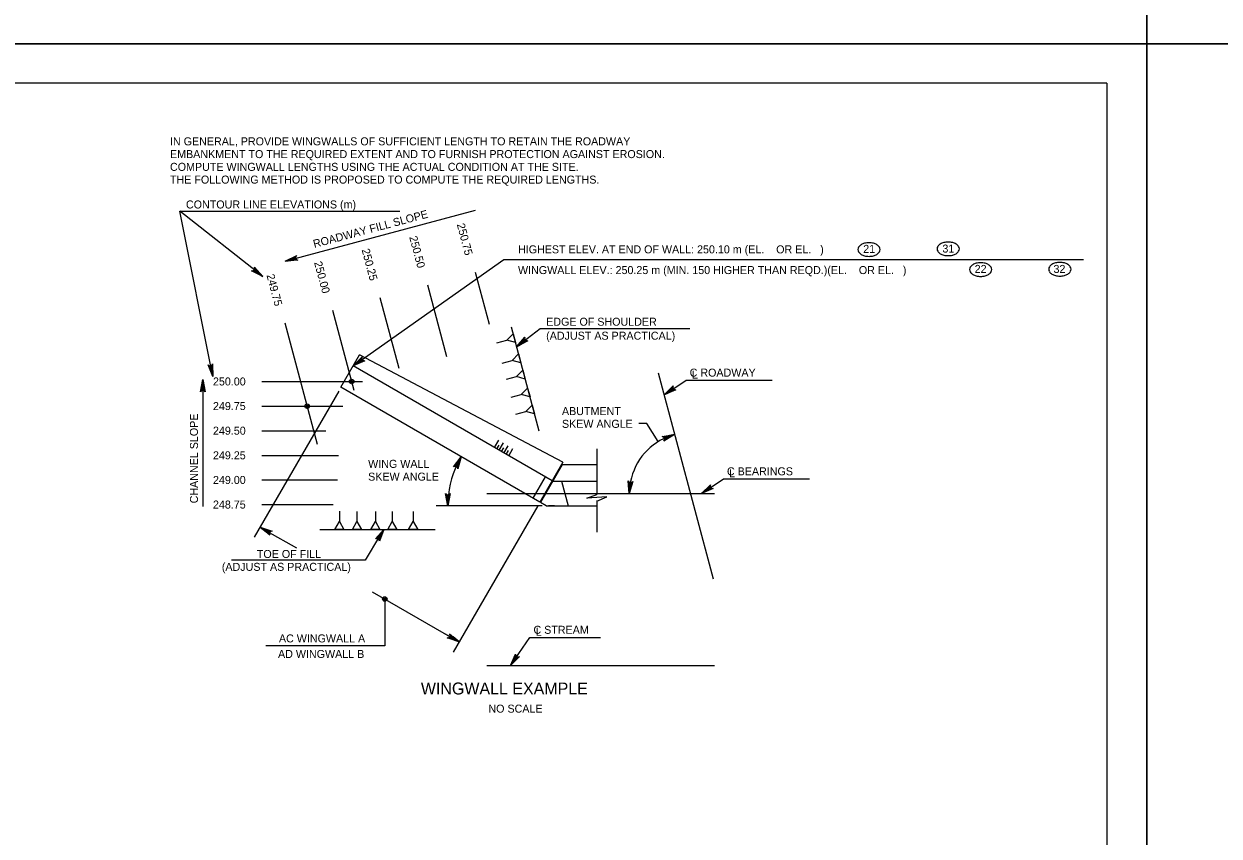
# Model space of a CAD drawing. Extents: x -5022 to -159, y 1126 to 7226.
# Drawn here: x -1737.9 to -1290, y 3798.9 to 4103.3 of the extents above; entities that cross this region are included whole.
import ezdxf

# ---------------------------------------------------------------- set-up
doc = ezdxf.new("R2010")
doc.units = 0
for name, color, linetype in [('2', 7, 'Continuous'), ('3', 7, 'Continuous'), ('4', 7, 'Continuous'), ('5', 7, 'Continuous'), ('6', 7, 'Continuous'), ('PLT-BNDY', 7, 'Continuous')]:
    doc.layers.add(name, color=color, linetype=linetype)

msp = doc.modelspace()

# ---------------------------------------------------------------- linework, layer by layer
at = {"layer": '2'}
for p, q in [((-1332.13, 4081.14), (-2118.13, 4081.14)), ((-1332.13, 4081.14), (-1332.13, 3517.14)), ((-1563.5, 3990.58), (-1568.7, 4010.1)), ((-1579.37, 3978.49), (-1586.53, 4005.35)), ((-1597.31, 3974.14), (-1604.37, 4000.6)), ((-1614.2, 3965.85), (-1622.2, 3995.84)), ((-1627.92, 3945.65), (-1640.03, 3991.09)), ((-1544.86, 3950.71), (-1555.24, 3989.67)), ((-1560.7, 3983.75), (-1556.99, 3984.74)), ((-1558.69, 3976.2), (-1554.97, 3977.19)), ((-1648.81, 3969.27), (-1611.06, 3969.27)), ((-1557.06, 3970.1), (-1553.35, 3971.09)), ((-1555.27, 3963.39), (-1551.56, 3964.38)), ((-1648.81, 3960.04), (-1618.35, 3960.04)), ((-1553.58, 3957.03), (-1549.86, 3958.02)), ((-1648.81, 3950.81), (-1624.83, 3950.81)), ((-1561.58, 3944.52), (-1559.99, 3947.26)), ((-1559.8, 3943.5), (-1558.22, 3946.23)), ((-1560.69, 3944.01), (-1559.88, 3945.41)), ((-1558.91, 3942.98), (-1558.1, 3944.39)), ((-1558.02, 3942.47), (-1556.45, 3945.21)), ((-1557.14, 3941.96), (-1556.33, 3943.36)), ((-1556.25, 3941.45), (-1554.67, 3944.19)), ((-1648.81, 3941.59), (-1619.97, 3941.59)), ((-1648.81, 3932.36), (-1620.37, 3932.36)), ((-1648.81, 3923.13), (-1621.99, 3923.13)), ((-1619.7, 3920.62), (-1619.71, 3916.77)), ((-1613.12, 3920.61), (-1613.12, 3916.76)), ((-1606.18, 3920.6), (-1606.18, 3916.76)), ((-1599.86, 3920.59), (-1599.86, 3916.75)), ((-1592.04, 3920.58), (-1592.05, 3916.74)), ((-1627.03, 3913.82), (-1583.78, 3913.82))]:
    msp.add_line(p, q, dxfattribs=at)
for points in [[(-1554.57, 3987.15), (-1553.69, 3983.86), (-1556.99, 3984.74)], [(-1552.56, 3979.6), (-1551.68, 3976.31), (-1554.97, 3977.19)], [(-1550.93, 3973.5), (-1550.05, 3970.2), (-1553.35, 3971.09)], [(-1549.14, 3966.79), (-1548.26, 3963.49), (-1551.56, 3964.38)], [(-1547.45, 3960.43), (-1546.57, 3957.13), (-1549.86, 3958.02)], [(-1618.01, 3913.82), (-1621.42, 3913.82), (-1619.71, 3916.77)], [(-1611.42, 3913.81), (-1614.83, 3913.81), (-1613.12, 3916.76)], [(-1604.48, 3913.8), (-1607.89, 3913.8), (-1606.18, 3916.76)], [(-1598.16, 3913.79), (-1601.57, 3913.8), (-1599.86, 3916.75)], [(-1590.35, 3913.78), (-1593.76, 3913.78), (-1592.05, 3916.74)]]:
    msp.add_lwpolyline(points, close=True, dxfattribs=at)
at = {"layer": '3'}
for p, q in [((-1679.45, 4033.13), (-1597.01, 4033.13)), ((-1558.01, 4015.05), (-1555.01, 4015.05)), ((-1555.01, 4015.05), (-1340.86, 4015.05)), ((-1550.92, 3984.17), (-1544.46, 3989.18)), ((-1544.46, 3989.18), (-1488.37, 3989.18)), ((-1495.5, 3965.92), (-1489.76, 3969.76)), ((-1489.76, 3969.76), (-1457.46, 3969.76)), ((-1619.95, 3965.7), (-1651.6, 3910.88)), ((-1504.42, 3953.52), (-1507.42, 3953.52)), ((-1500.21, 3946.74), (-1504.42, 3953.52)), ((-1481.53, 3928.93), (-1475.79, 3932.77)), ((-1475.79, 3932.77), (-1443.48, 3932.77)), ((-1543.73, 3922.67), (-1583.46, 3922.67)), ((-1545.32, 3922.71), (-1577.01, 3867.82)), ((-1646.83, 3913.24), (-1635.81, 3906.88)), ((-1604.61, 3911.25), (-1610, 3902.28)), ((-1613, 3902.28), (-1660.1, 3902.28)), ((-1610, 3902.28), (-1613, 3902.28)), ((-1607.39, 3890.47), (-1577.35, 3873.13)), ((-1602.68, 3887.75), (-1602.68, 3870.24)), ((-1577.35, 3873.13), (-1579.91, 3874.6)), ((-1602.68, 3870.24), (-1647.27, 3870.24)), ((-1553.87, 3865.28), (-1548.29, 3873.37)), ((-1548.29, 3873.37), (-1521.82, 3873.37))]:
    msp.add_line(p, q, dxfattribs=at)
for points in [[(-1648.42, 4008.6), (-1679.45, 4033.13)], [(-1667.17, 3971.15), (-1679.45, 4033.13)], [(-1639.98, 4014.42), (-1568.65, 4033.43)], [(-1639.98, 4014.42), (-1635.7, 4016.46), (-1635.99, 4016.13), (-1636.09, 4015.78), (-1636.06, 4015.46), (-1635.92, 4015.17), (-1635.67, 4014.92), (-1635.25, 4014.77), (-1639.98, 4014.42), (-1635.67, 4014.92), (-1635.92, 4015.17), (-1639.98, 4014.42), (-1636.06, 4015.46), (-1636.09, 4015.78), (-1639.98, 4014.42), (-1635.99, 4016.13)], [(-1614.52, 3975.09), (-1558.01, 4015.05)], [(-1648.42, 4008.6), (-1652.62, 4010.81), (-1652.19, 4010.78), (-1651.85, 4010.91), (-1651.61, 4011.12), (-1651.46, 4011.4), (-1651.41, 4011.76), (-1651.54, 4012.18), (-1648.42, 4008.6), (-1651.41, 4011.76), (-1651.46, 4011.4), (-1648.42, 4008.6), (-1651.61, 4011.12), (-1651.85, 4010.91), (-1648.42, 4008.6), (-1652.19, 4010.78)], [(-1553.29, 3982.33), (-1550.14, 3985.88), (-1550.27, 3985.47), (-1550.23, 3985.1), (-1550.08, 3984.82), (-1549.84, 3984.61), (-1549.51, 3984.48), (-1549.07, 3984.5), (-1553.29, 3982.33), (-1549.51, 3984.48), (-1549.84, 3984.61), (-1553.29, 3982.33), (-1550.08, 3984.82), (-1550.23, 3985.1), (-1553.29, 3982.33), (-1550.27, 3985.47)], [(-1614.52, 3975.09), (-1611.22, 3978.5), (-1611.37, 3978.09), (-1611.34, 3977.72), (-1611.21, 3977.44), (-1610.98, 3977.21), (-1610.65, 3977.06), (-1610.21, 3977.07), (-1614.52, 3975.09), (-1610.65, 3977.06), (-1610.98, 3977.21), (-1614.52, 3975.09), (-1611.21, 3977.44), (-1611.34, 3977.72), (-1614.52, 3975.09), (-1611.37, 3978.09)], [(-1667.17, 3971.15), (-1668.93, 3975.56), (-1668.62, 3975.25), (-1668.28, 3975.13), (-1667.96, 3975.14), (-1667.66, 3975.25), (-1667.39, 3975.5), (-1667.22, 3975.89), (-1667.17, 3971.15), (-1667.39, 3975.5), (-1667.66, 3975.25), (-1667.17, 3971.15), (-1667.96, 3975.14), (-1668.28, 3975.13), (-1667.17, 3971.15), (-1668.62, 3975.25)], [(-1670.85, 3970.05), (-1669.97, 3965.39), (-1670.22, 3965.75), (-1670.53, 3965.93), (-1670.85, 3965.98), (-1671.16, 3965.93), (-1671.47, 3965.75), (-1671.72, 3965.39), (-1670.85, 3970.05), (-1671.47, 3965.75), (-1671.16, 3965.93), (-1670.85, 3970.05), (-1670.85, 3965.98), (-1670.53, 3965.93), (-1670.85, 3970.05), (-1670.22, 3965.75)], [(-1670.85, 3970.05), (-1670.85, 3922.37)], [(-1497.96, 3964.28), (-1494.57, 3967.59), (-1494.73, 3967.19), (-1494.71, 3966.83), (-1494.58, 3966.54), (-1494.36, 3966.31), (-1494.03, 3966.15), (-1493.6, 3966.14), (-1497.96, 3964.28), (-1494.03, 3966.15), (-1494.36, 3966.31), (-1497.96, 3964.28), (-1494.58, 3966.54), (-1494.71, 3966.83), (-1497.96, 3964.28), (-1494.73, 3967.19)], [(-1494.07, 3949.42), (-1498.13, 3946.97), (-1497.88, 3947.33), (-1497.82, 3947.69), (-1497.88, 3948), (-1498.03, 3948.27), (-1498.32, 3948.5), (-1498.74, 3948.61), (-1494.07, 3949.42), (-1498.32, 3948.5), (-1498.03, 3948.27), (-1494.07, 3949.42), (-1497.88, 3948), (-1497.82, 3947.69), (-1494.07, 3949.42), (-1497.88, 3947.33)], [(-1574.09, 3941.09), (-1575.3, 3936.51), (-1575.37, 3936.94), (-1575.57, 3937.24), (-1575.83, 3937.42), (-1576.14, 3937.51), (-1576.5, 3937.47), (-1576.88, 3937.26), (-1574.09, 3941.09), (-1576.5, 3937.47), (-1576.14, 3937.51), (-1574.09, 3941.09), (-1575.83, 3937.42), (-1575.57, 3937.24), (-1574.09, 3941.09), (-1575.37, 3936.94)], [(-1511.04, 3927.29), (-1511.48, 3932.01), (-1511.26, 3931.63), (-1510.97, 3931.41), (-1510.66, 3931.33), (-1510.35, 3931.36), (-1510.02, 3931.51), (-1509.74, 3931.85), (-1511.04, 3927.29), (-1510.02, 3931.51), (-1510.35, 3931.36), (-1511.04, 3927.29), (-1510.66, 3931.33), (-1510.97, 3931.41), (-1511.04, 3927.29), (-1511.26, 3931.63)], [(-1483.98, 3927.29), (-1480.6, 3930.6), (-1480.76, 3930.2), (-1480.74, 3929.83), (-1480.61, 3929.54), (-1480.39, 3929.31), (-1480.06, 3929.16), (-1479.62, 3929.15), (-1483.98, 3927.29), (-1480.06, 3929.16), (-1480.39, 3929.31), (-1483.98, 3927.29), (-1480.61, 3929.54), (-1480.74, 3929.83), (-1483.98, 3927.29), (-1480.76, 3930.2)], [(-1579.03, 3922.67), (-1579.9, 3927.33), (-1579.65, 3926.98), (-1579.34, 3926.79), (-1579.03, 3926.73), (-1578.71, 3926.79), (-1578.4, 3926.98), (-1578.15, 3927.33), (-1579.03, 3922.67), (-1578.4, 3926.98), (-1578.71, 3926.79), (-1579.03, 3922.67), (-1579.03, 3926.73), (-1579.34, 3926.79), (-1579.03, 3922.67), (-1579.65, 3926.98)], [(-1649.38, 3914.72), (-1644.91, 3913.14), (-1645.34, 3913.11), (-1645.66, 3912.93), (-1645.86, 3912.68), (-1645.97, 3912.39), (-1645.97, 3912.02), (-1645.78, 3911.63), (-1649.38, 3914.72), (-1645.97, 3912.02), (-1645.97, 3912.39), (-1649.38, 3914.72), (-1645.86, 3912.68), (-1645.66, 3912.93), (-1649.38, 3914.72), (-1645.34, 3913.11)], [(-1603.07, 3913.82), (-1604.72, 3909.37), (-1604.75, 3909.81), (-1604.92, 3910.13), (-1605.16, 3910.34), (-1605.46, 3910.45), (-1605.82, 3910.45), (-1606.22, 3910.27), (-1603.07, 3913.82), (-1605.82, 3910.45), (-1605.46, 3910.45), (-1603.07, 3913.82), (-1605.16, 3910.34), (-1604.92, 3910.13), (-1603.07, 3913.82), (-1604.75, 3909.81)], [(-1574.8, 3871.65), (-1579.27, 3873.23), (-1578.83, 3873.26), (-1578.52, 3873.44), (-1578.32, 3873.68), (-1578.21, 3873.98), (-1578.21, 3874.34), (-1578.4, 3874.74), (-1574.8, 3871.65), (-1578.21, 3874.34), (-1578.21, 3873.98), (-1574.8, 3871.65), (-1578.32, 3873.68), (-1578.52, 3873.44), (-1574.8, 3871.65), (-1578.83, 3873.26)], [(-1555.58, 3862.81), (-1553.65, 3867.14), (-1553.65, 3866.7), (-1553.5, 3866.37), (-1553.27, 3866.15), (-1552.98, 3866.02), (-1552.62, 3865.99), (-1552.21, 3866.15), (-1555.58, 3862.81), (-1552.62, 3865.99), (-1552.98, 3866.02), (-1555.58, 3862.81), (-1553.27, 3866.15), (-1553.5, 3866.37), (-1555.58, 3862.81), (-1553.65, 3866.7)]]:
    msp.add_lwpolyline(points, dxfattribs=at)
for points in [[(-1639.98, 4014.42), (-1637.02, 4014.95), (-1637.15, 4015.43)], [(-1648.42, 4008.6), (-1650.62, 4010.66), (-1650.93, 4010.26)], [(-1550.61, 3983.78), (-1551.22, 3984.57), (-1553.29, 3982.33)], [(-1667.17, 3971.15), (-1667.51, 3974.15), (-1668, 3974.05)], [(-1614.52, 3975.09), (-1611.93, 3976.62), (-1612.22, 3977.03)], [(-1670.85, 3970.05), (-1671.1, 3967.05), (-1670.6, 3967.05)], [(-1495.77, 3966.33), (-1495.23, 3965.51), (-1497.96, 3964.28)], [(-1496.7, 3947.99), (-1497.02, 3948.93), (-1494.07, 3949.41)], [(-1575.9, 3938.71), (-1575.03, 3938.25), (-1574.09, 3941.09)], [(-1511.34, 3930.27), (-1510.36, 3930.2), (-1511.04, 3927.29)], [(-1481.8, 3929.34), (-1481.26, 3928.52), (-1483.98, 3927.29)], [(-1578.41, 3925.6), (-1579.4, 3925.64), (-1579.03, 3922.67)], [(-1646.58, 3913.67), (-1647.07, 3912.81), (-1649.38, 3914.72)], [(-1605.04, 3911.51), (-1604.18, 3910.99), (-1603.07, 3913.82)], [(-1577.11, 3873.55), (-1577.6, 3872.7), (-1574.8, 3871.65)], [(-1553.46, 3864.99), (-1554.29, 3865.56), (-1555.58, 3862.81)]]:
    msp.add_lwpolyline(points, close=True, dxfattribs=at)
for radius in [0.833, 0.417]:
    msp.add_circle((-1602.68, 3887.75), radius, dxfattribs=at)
for centre, radius, start, end in [((-1423.79, 4018.74), 1.61, 145.8704, 180), ((-1423.79, 4018.74), 1.61, 180, 214.1296), ((-1422.56, 4017.9), 3.1, 121.4296, 145.8704), ((-1421.75, 4016.57), 4.65, 104.2049, 121.4296), ((-1421.21, 4014.47), 6.82, 90, 104.2049), ((-1421.21, 4014.47), 6.82, 75.7951, 90), ((-1420.68, 4016.57), 4.65, 58.5704, 75.7951), ((-1419.87, 4017.9), 3.1, 34.1296, 58.5704), ((-1418.64, 4018.74), 1.61, 0, 34.1296), ((-1418.64, 4018.74), 1.61, 325.8704, 0), ((-1394.11, 4018.99), 1.61, 145.8704, 180), ((-1394.11, 4018.99), 1.61, 180, 214.1296), ((-1392.88, 4018.16), 3.1, 121.4296, 145.8704), ((-1392.88, 4019.82), 3.1, 214.1296, 238.5704), ((-1392.07, 4016.83), 4.65, 104.2049, 121.4296), ((-1391.54, 4014.72), 6.82, 90, 104.2049), ((-1391.54, 4014.72), 6.82, 75.7951, 90), ((-1391, 4016.83), 4.65, 58.5704, 75.7951), ((-1390.19, 4018.16), 3.1, 34.1296, 58.5704), ((-1390.19, 4019.82), 3.1, 301.4296, 325.8704), ((-1388.96, 4018.99), 1.61, 0, 34.1296), ((-1388.96, 4018.99), 1.61, 325.8704, 0), ((-1422.56, 4019.57), 3.1, 214.1296, 238.5704), ((-1421.75, 4020.9), 4.65, 238.5704, 255.7951), ((-1421.21, 4023), 6.82, 255.7951, 270), ((-1421.21, 4023), 6.82, 270, 284.2049), ((-1420.68, 4020.9), 4.65, 284.2049, 301.4296), ((-1419.87, 4019.57), 3.1, 301.4296, 325.8704), ((-1392.07, 4021.15), 4.65, 238.5704, 255.7951), ((-1391.54, 4023.26), 6.82, 255.7951, 270), ((-1391.54, 4023.26), 6.82, 270, 284.2049), ((-1391, 4021.15), 4.65, 284.2049, 301.4296), ((-1379.9, 4009.06), 4.65, 104.2049, 121.4296), ((-1379.36, 4006.96), 6.82, 90, 104.2049), ((-1379.36, 4006.96), 6.82, 75.7951, 90), ((-1378.83, 4009.06), 4.65, 58.5704, 75.7951), ((-1350.22, 4009.19), 4.65, 104.2049, 121.4296), ((-1349.68, 4007.08), 6.82, 90, 104.2049), ((-1349.68, 4007.08), 6.82, 75.7951, 90), ((-1349.15, 4009.19), 4.65, 58.5704, 75.7951), ((-1381.94, 4011.22), 1.61, 145.8704, 180), ((-1381.94, 4011.22), 1.61, 180, 214.1296), ((-1380.71, 4010.39), 3.1, 121.4296, 145.8704), ((-1380.71, 4012.06), 3.1, 214.1296, 238.5704), ((-1379.9, 4013.39), 4.65, 238.5704, 255.7951), ((-1378.83, 4013.39), 4.65, 284.2049, 301.4296), ((-1378.02, 4010.39), 3.1, 34.1296, 58.5704), ((-1378.02, 4012.06), 3.1, 301.4296, 325.8704), ((-1376.79, 4011.22), 1.61, 0, 34.1296), ((-1376.79, 4011.22), 1.61, 325.8704, 0), ((-1352.26, 4011.35), 1.61, 145.8704, 180), ((-1352.26, 4011.35), 1.61, 180, 214.1296), ((-1351.03, 4010.52), 3.1, 121.4296, 145.8704), ((-1351.03, 4012.18), 3.1, 214.1296, 238.5704), ((-1350.22, 4013.51), 4.65, 238.5704, 255.7951), ((-1349.68, 4015.62), 6.82, 255.7951, 270), ((-1349.68, 4015.62), 6.82, 270, 284.2049), ((-1349.15, 4013.51), 4.65, 284.2049, 301.4296), ((-1348.34, 4010.52), 3.1, 34.1296, 58.5704), ((-1348.34, 4012.18), 3.1, 301.4296, 325.8704), ((-1347.11, 4011.35), 1.61, 0, 34.1296), ((-1347.11, 4011.35), 1.61, 325.8704, 0), ((-1379.36, 4015.49), 6.82, 255.7951, 270), ((-1379.36, 4015.49), 6.82, 270, 284.2049), ((-1488.14, 3927.29), 22.9, 112.393, 172.6069), ((-1542.19, 3922.67), 36.84, 154.594, 180), ((-1542.19, 3922.67), 36.84, 174.95, 175.4061)]:
    msp.add_arc(centre, radius, start, end, dxfattribs=at)
at = {"layer": '4'}
for p, q in [((-1523.26, 3944.1), (-1523.26, 3926.98)), ((-1523.26, 3924.63), (-1523.26, 3912.76))]:
    msp.add_line(p, q, dxfattribs=at)
msp.add_lwpolyline([(-1523.26, 3924.48), (-1519.51, 3926), (-1527.01, 3925.55), (-1523.26, 3926.98)], dxfattribs=at)
at = {"layer": '5'}
for p, q in [((-1619.14, 3967.1), (-1612.12, 3979.26)), ((-1535.9, 3939.02), (-1612.12, 3979.26)), ((-1539.94, 3932.03), (-1614.52, 3975.09)), ((-1544.55, 3924.04), (-1619.14, 3967.1)), ((-1535.9, 3939.02), (-1544.55, 3924.04)), ((-1536.19, 3938), (-1544.33, 3923.91)), ((-1523.26, 3937.99), (-1536.19, 3938)), ((-1542.6, 3933.57), (-1547.22, 3925.57)), ((-1539.72, 3931.9), (-1523.26, 3931.9)), ((-1536.49, 3931.9), (-1534.01, 3922.67)), ((-1564.47, 3927.29), (-1479.15, 3927.29)), ((-1542.19, 3922.67), (-1544.33, 3923.91)), ((-1542.19, 3922.67), (-1523.26, 3922.67)), ((-1539.11, 3922.67), (-1541.34, 3922.67)), ((-1564.47, 3862.81), (-1479.15, 3862.81))]:
    msp.add_line(p, q, dxfattribs=at)
for centre, radius in [((-1615.11, 3969.27), 0.833), ((-1615.11, 3969.27), 0.417), ((-1631.75, 3960.04), 0.833), ((-1631.75, 3960.04), 0.417)]:
    msp.add_circle(centre, radius, dxfattribs=at)
at = {"layer": '6'}
msp.add_line((-1479.53, 3895.16), (-1500.11, 3972.36), dxfattribs=at)
at = {"layer": 'PLT-BNDY'}
for points in [[(-2158.13, 4689.81), (-1317.13, 4689.81), (-1317.13, 4095.81), (-2158.13, 4095.81)], [(-1317.13, 4689.81), (-476.13, 4689.81), (-476.13, 4095.81), (-1317.13, 4095.81)], [(-2158.13, 4095.81), (-1317.13, 4095.81), (-1317.13, 3501.81), (-2158.13, 3501.81)], [(-1317.13, 4095.81), (-476.13, 4095.81), (-476.13, 3501.81), (-1317.13, 3501.81)]]:
    msp.add_lwpolyline(points, close=True, dxfattribs=at)

# ---------------------------------------------------------------- texts
at = {"layer": '3'}
for s, height, p in [('IN GENERAL, PROVIDE WINGWALLS OF SUFFICIENT LENGTH TO RETAIN THE ROADWAY', 3.0001, (-1683.18, 4057.79)), ('EMBANKMENT TO THE REQUIRED EXTENT AND TO FURNISH PROTECTION AGAINST EROSION.', 3.0001, (-1683.18, 4053.01)), ('COMPUTE WINGWALL LENGTHS USING THE ACTUAL CONDITION AT THE SITE.', 3.0001, (-1683.18, 4048.23)), ('THE FOLLOWING METHOD IS PROPOSED TO COMPUTE THE REQUIRED LENGTHS.', 3.0001, (-1683.18, 4043.45)), ('CONTOUR LINE ELEVATIONS (m)', 3.0001, (-1677.2, 4034.13)), ('HIGHEST ELEV. AT END OF WALL: 250.10 m (EL.    OR EL.   )', 3.0001, (-1552.76, 4017.3)), ('21', 3, (-1423.38, 4017.48)), ('31', 3, (-1393.7, 4017.6)), ('WINGWALL ELEV.: 250.25 m (MIN. 150 HIGHER THAN REQD.)(EL.    OR EL.   )', 3.0001, (-1552.76, 4009.54)), ('22', 3, (-1381.62, 4009.97)), ('32', 3, (-1352.07, 4009.97)), ('EDGE OF SHOULDER', 3.0001, (-1542.21, 3990.18)), ('(ADJUST AS PRACTICAL)', 3.0001, (-1542.21, 3984.94)), ('C ROADWAY', 3, (-1488.43, 3971.1)), ('L', 3, (-1487.57, 3970.35)), ('250.00', 3, (-1667.08, 3967.79)), ('249.75', 3, (-1667.08, 3958.57)), ('ABUTMENT', 3, (-1536.29, 3956.69)), ('249.50', 3, (-1667.08, 3949.34)), ('SKEW ANGLE', 3, (-1536.29, 3951.91)), ('249.25', 3, (-1667.08, 3940.11)), ('WING WALL', 3, (-1608.92, 3936.91)), ('249.00', 3, (-1667.08, 3930.88)), ('SKEW ANGLE', 3, (-1608.92, 3932.12)), ('C BEARINGS', 3, (-1474.46, 3934.11)), ('L', 3, (-1473.6, 3933.36)), ('248.75', 3, (-1667.08, 3921.66)), ('TOE OF FILL', 3.0001, (-1650.63, 3903.13)), ('(ADJUST AS PRACTICAL)', 3.0001, (-1663.76, 3898.31)), ('AC WINGWALL A', 3.0001, (-1642.35, 3871.48)), ('C STREAM', 3, (-1546.96, 3874.71)), ('L', 3, (-1546.1, 3873.97)), ('AD WINGWALL B', 3.0001, (-1642.69, 3865.65)), ('WINGWALL EXAMPLE', 4.4793, (-1589.16, 3851.97)), ('NO SCALE', 3, (-1563.85, 3845.16))]:
    msp.add_text(s, height=height, dxfattribs=at).set_placement(p)
for s, height, rotation, p in [('ROADWAY FILL SLOPE', 3.0001, 14.927, (-1629.09, 4019.32)), ('250.75', 3, 284.927, (-1575.72, 4028.14)), ('250.50', 3, 284.927, (-1593.55, 4023.39)), ('250.25', 3, 284.927, (-1611.38, 4018.64)), ('250.00', 3, 284.927, (-1629.22, 4013.89)), ('249.75', 3, 284.927, (-1647.05, 4009.13)), ('CHANNEL SLOPE', 3.0001, 90, (-1672.7, 3923.6))]:
    msp.add_text(s, height=height, rotation=rotation, dxfattribs=at).set_placement(p)

doc.saveas('drawing.dxf')
